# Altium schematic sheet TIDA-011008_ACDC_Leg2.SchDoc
size 431 x 279 mm; Date: Not shown in title block; ApprovedBy: Not shown in title block; CheckedBy: Not shown in title block; Author: Not shown in title block; CompanyName: Not shown in title block; Engineer: Not shown in title block; Organization: Not shown in title block; Address1: Not shown in title block; Address2: Not shown in title block; Address3: Not shown in title block; Address4: Not shown in title block; DocumentNumber: 1; Revision: Use project parameter SCH_Rev; SheetNumber: 5; SheetTotal: 12; PageSetup: Record=PageOptions¦CenterHorizontal=True¦CenterVertical=True¦PrintScale=1.00¦XCorrection=1.00¦YCorrection=1.00¦PrintKind=0¦BorderSize=5000000¦LeftOffset=0¦BottomOffset=0¦Orientation=2¦PaperLength=1000¦PaperWidth=1000¦Scale=100¦PaperSource=15¦PrintQuality=600¦MediaType=1¦DitherType=10¦PaperKind=Letter¦PrintScaleMode=1
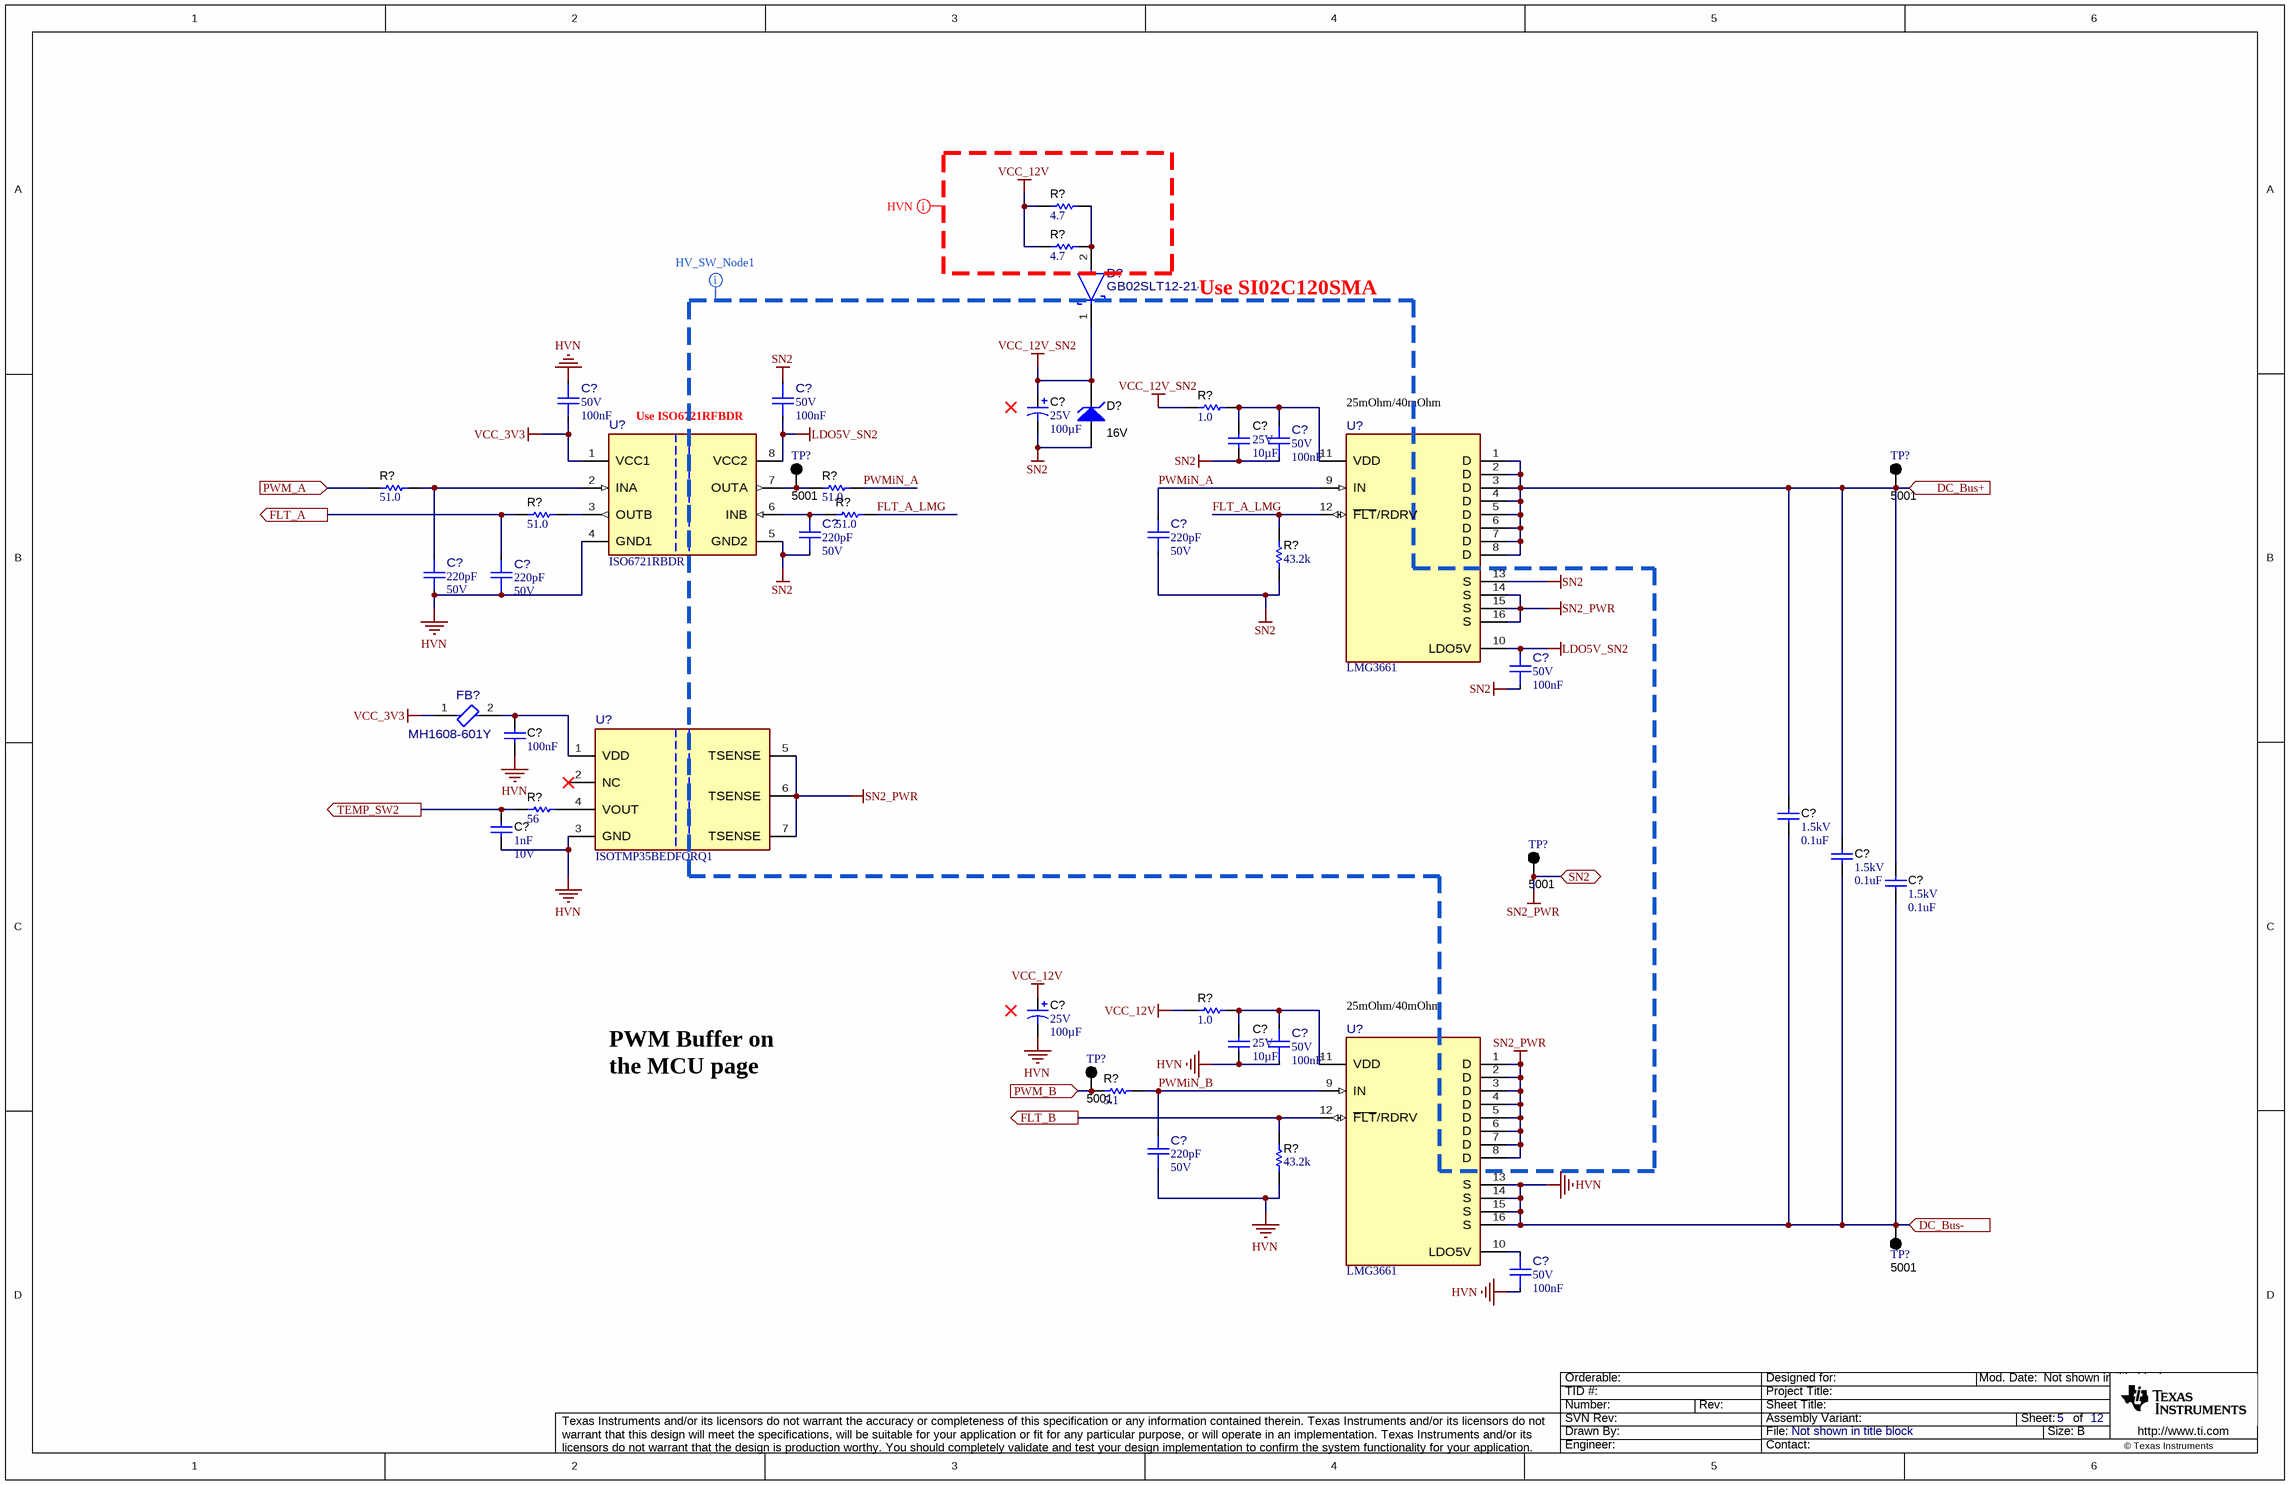
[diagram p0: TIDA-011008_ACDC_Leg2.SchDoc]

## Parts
(Parts that share a designator on the sheet are numbered #1, #2 ... from top to bottom, then left to right.)
C?#1  VDC_V: 50V  Cap_F: 100nF  [FP-GCM188R71H104KA57J_0603-MFG]  (hidden comment: GCM188R71H104KA57J)
C?#2  VDC_V: 50V  Cap_F: 100nF  [FP-GCM188R71H104KA57J_0603-MFG]  (hidden comment: GCM188R71H104KA57J)
C?#3  VDC_V: 25V  ValueDisplayed: 100µF  [UWT_630x770]  (hidden comment: UWT1E101MCL1GS)
C?#4  VDC_V: 25V  ValueDisplayed: 10µF  [1206_180]  (hidden comment: TMK316AB7106KLHT)
C?#5  VDC_V: 50V  Cap_F: 100nF  [FP-GCM188R71H104KA57J_0603-MFG]  (hidden comment: GCM188R71H104KA57J)
C?#6  ValueDisplayed: 220pF  VDC_V: 50V  [FP-C0603C221J5GAC7867_0603-MFG]  (hidden comment: C0603C221J5GAC7867)
C?#7  ValueDisplayed: 220pF  VDC_V: 50V  [FP-C0603C221J5GAC7867_0603-MFG]  (hidden comment: C0603C221J5GAC7867)
C?#8  ValueDisplayed: 220pF  VDC_V: 50V  [FP-C0603C221J5GAC7867_0603-MFG]  (hidden comment: C0603C221J5GAC7867)
C?#9  ValueDisplayed: 220pF  VDC_V: 50V  [FP-C0603C221J5GAC7867_0603-MFG]  (hidden comment: C0603C221J5GAC7867)
C?#10  VDC_V: 50V  Cap_F: 100nF  [FP-GCM188R71H104KA57J_0603-MFG]  (hidden comment: GCM188R71H104KA57J)
C?#11  Cap_F: 100nF  [0603]  (hidden comment: 06033C104JAT2A)
C?#12  VDC_V: 1.5kV  ValueDisplayed: 0.1uF  [2225]  (hidden comment: C2225C104KFRACTU)
C?#13  Cap_F: 1nF  VDC_V: 10V  [0603]  (hidden comment: 0603ZC102KAT2A)
C?#14  VDC_V: 1.5kV  ValueDisplayed: 0.1uF  [2225]  (hidden comment: C2225C104KFRACTU)
C?#15  VDC_V: 1.5kV  ValueDisplayed: 0.1uF  [2225]  (hidden comment: C2225C104KFRACTU)
C?#16  VDC_V: 25V  ValueDisplayed: 100µF  [UWT_630x770]  (hidden comment: UWT1E101MCL1GS)
C?#17  VDC_V: 25V  ValueDisplayed: 10µF  [1206_180]  (hidden comment: TMK316AB7106KLHT)
C?#18  VDC_V: 50V  Cap_F: 100nF  [FP-GCM188R71H104KA57J_0603-MFG]  (hidden comment: GCM188R71H104KA57J)
C?#19  ValueDisplayed: 220pF  VDC_V: 50V  [FP-C0603C221J5GAC7867_0603-MFG]  (hidden comment: C0603C221J5GAC7867)
C?#20  VDC_V: 50V  Cap_F: 100nF  [FP-GCM188R71H104KA57J_0603-MFG]  (hidden comment: GCM188R71H104KA57J)
D?#1  GB02SLT12-214  [FP-GB02SLT12-214_DO-214AA-MFG]
D?#2  value 16V  [SOD-123]  (hidden comment: BZT52C16-7-F)
FB?  MH1608-601Y  [FP-MH1608-601Y_0603-MFG]
R?#1  ValueDisplayed: 4.7  [1206]  (hidden comment: CRCW12064R70JNEAHP)
R?#2  ValueDisplayed: 4.7  [1206]  (hidden comment: CRCW12064R70JNEAHP)
R?#3  ValueDisplayed: 1.0  [0603]  (hidden comment: CRCW06031R00JNEA)
R?#4  ValueDisplayed: 51.0  [0603]  (hidden comment: RC0603FR-0751RL)
R?#5  ValueDisplayed: 51.0  [0603]  (hidden comment: RC0603FR-0751RL)
R?#6  ValueDisplayed: 51.0  [0603]  (hidden comment: RC0603FR-0751RL)
R?#7  ValueDisplayed: 51.0  [0603]  (hidden comment: RC0603FR-0751RL)
R?#8  ValueDisplayed: 43.2k  [0603]  (hidden comment: RC0603FR-0743K2L)
R?#9  ValueDisplayed: 56  [0603]  (hidden comment: RG1608P-560-B-T5)
R?#10  ValueDisplayed: 1.0  [0603]  (hidden comment: CRCW06031R00JNEA)
R?#11  ValueDisplayed: 5.1  [0603]  (hidden comment: CRCW06035R10JNEA)
R?#12  ValueDisplayed: 43.2k  [0603]  (hidden comment: RC0603FR-0743K2L)
TP?#1  5001  [Keystone5001]
TP?#2  5001  [Keystone5001]
TP?#3  5001  [Keystone5001]
TP?#4  5001  [Keystone5001]
TP?#5  5001  [Keystone5001]
U?#1  ISO6721RBDR  [D0008A-MFG]
U?#2  LMG3661  [KLF0016A-MFG]
U?#3  ISOTMP35BEDFQRQ1  [DFQ0007A-MFG]
U?#4  LMG3661  [KLF0016A-MFG]

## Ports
DC_Bus+ (in), DC_Bus- (in), FLT_A (out), FLT_B (out), PWM_A (in), PWM_B (in), SN2 (bidir), TEMP_SW2 (out)

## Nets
HVN: C?#1.1 C?#6.2 C?#9.1 C?#11.2 C?#12.2 C?#13.2 C?#14.2 C?#15.2 C?#16.2(-) C?#17.2 C?#18.1 C?#19.1 C?#20.1 R?#12.1 TP?#5.1 U?#1.4(GND1) U?#3.3(GND) U?#4.13(S) U?#4.14(S) U?#4.15(S) U?#4.16(S) ; port DC_Bus-
LDO5V_SN2: C?#2.2 C?#10.2 U?#1.8(VCC2) U?#2.10(LDO5V)
SN2: C?#2.1 C?#3.2(-) C?#4.2 C?#5.1 C?#7.1 C?#8.1 C?#10.1 D?#2.2(A) R?#8.1 U?#1.5(GND2) U?#2.13(S)
SN2_PWR: TP?#3.1 U?#2.14(S) U?#2.15(S) U?#2.16(S) U?#3.5(TSENSE) U?#3.6(TSENSE) U?#3.7(TSENSE) U?#4.1(D) U?#4.2(D) U?#4.3(D) U?#4.4(D) U?#4.5(D) U?#4.6(D) U?#4.7(D) U?#4.8(D) ; port SN2
VCC_3V3: C?#1.2 FB?.1 U?#1.1(VCC1)
VCC_12V: C?#16.1(+) R?#1.1 R?#2.1 R?#10.1
VCC_12V_SN2: C?#3.1(+) D?#1.1(CATHODE) D?#2.1(K) R?#3.1
DC_Bus+: C?#12.1 C?#14.1 C?#15.1 TP?#2.1 U?#2.1(D) U?#2.2(D) U?#2.3(D) U?#2.4(D) U?#2.5(D) U?#2.6(D) U?#2.7(D) U?#2.8(D) ; port DC_Bus+
FLT_A: C?#9.2 R?#6.1 ; port FLT_A
FLT_A_LMG: R?#7.2 R?#8.2 U?#2.12(~{FLT}/RDRV)
FLT_B: R?#12.2 U?#4.12(~{FLT}/RDRV) ; port FLT_B
PWM_A: R?#4.1 ; port PWM_A
PWM_B: R?#11.1 TP?#4.1 ; port PWM_B
PWMiN_A: C?#8.2 R?#5.2 U?#2.9(IN)
PWMiN_B: C?#19.2 R?#11.2 U?#4.9(IN)
TEMP_SW2: C?#13.1 R?#9.1 ; port TEMP_SW2
NetC?#4_1: C?#4.1 C?#5.2 R?#3.2 U?#2.11(VDD)
NetC?#6_1: C?#6.1 R?#4.2 U?#1.2(INA)
NetC?#7_2: C?#7.2 R?#7.1 U?#1.6(INB)
NetC?#11_1: C?#11.1 FB?.2 U?#3.1(VDD)
NetC?#17_1: C?#17.1 C?#18.2 R?#10.2 U?#4.11(VDD)
NetC?#20_2: C?#20.2 U?#4.10(LDO5V)
NetD?#1_2: D?#1.2(ANODE) R?#1.2 R?#2.2
NetR?#5_1: R?#5.1 TP?#1.1 U?#1.7(OUTA)
NetR?#6_2: R?#6.2 U?#1.3(OUTB)
NetR?#9_2: R?#9.2 U?#3.4(VOUT)

Not connected (* = marked no-connect by the designer): U?#3 2(NC)*

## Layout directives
net class HV_SW_Node1: FLT_A_LMG, HVN, LDO5V_SN2, PWMiN_A, PWMiN_B, SN2, SN2_PWR, VCC_12V, VCC_12V_SN2
net class HVN: VCC_12V

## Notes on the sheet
- Use SI02C120SMA
- Use ISO6721RFBDR
- 25mOhm/40mOhm
- PWM Buffer on the MCU page

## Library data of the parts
C?#1 C?#2 C?#5 C?#10 C?#18 C?#20 = CMP-0095617-1: 0603 50 V 0.1 uF X7R ±10% Tolerance SMT Multilayer Ceramic Capacitor; Manufacturer: Murata; TempCo: 15%; SizeZ_mm: 0.9mm; AEC Qualified: No; ValueDisplayed: 0.1uF; Value: 100nF
C?#3 C?#16 = CMP-0081462-1: CAP, AL, 100 µF, 25 V, +/- 20%, SMD; Manufacturer: Nichicon; TaMin_C: -55°C; Polarized: Y; SizeAreaWB_mm2: 77.4; U/M: EA; Value: 100uF; TaMax_C: 105°C; SizeZ_mm: 8; SizeX_mm: 7; SizeY_mm: 6.6; Cap_Case: 6.3x7.7mm; SizeArea_mm2: 46.2; CompType: Capacitor; AEC Qualified: N; IRMS_A: 91mA; AEC Category: Q200
C?#4 C?#17 = CMP-0750154-1: CAP, CERM, 10 µF, 25 V,+/- 10%, X7R, AEC-Q200 Grade 1, 1206; Manufacturer: Taiyo Yuden; AEC Qualified: Y; SizeZ_mm: 1.8; TaMax_C: 125°C; TaMin_C: -55°C; Cap_Case: 1206; Polarized: N; AEC Grade: 1; SizeY_mm: 1.6; Value: 10uF; SizeX_mm: 3.2; SizeAreaWB_mm2: 10.92; AEC Category: Q200; U/M: EA; SizeArea_mm2: 5.12
C?#6-C?#9 C?#19 = CMP-0045670-1: 220 pF ±5% 50V Ceramic Capacitor C0G, NP0 0603 (1608 Metric); Manufacturer: KEMET; AEC Qualified: No; SizeZ_mm: 0.87mm; TempCo: 30ppm/°C; Value: 220pF
C?#11 = CMP-0006752-5: CAP, CERM, 0.1 uF, 25 V, +/- 5%, X7R, 0603; Manufacturer: AVX; TaMin_C: -55°C; ESR_ohm: 0.05; Polarized: N; SizeAreaWB_mm2: 4.68; Value1: 0.05 ohm; U/M: EA; Value: 0.1uF; TaMax_C: 125°C; SizeZ_mm: 1; SizeX_mm: 1.6; SizeY_mm: 0.8; Value2: 25V; SizeArea_mm2: 1.28; AEC Category: Q200
C?#12 C?#14 C?#15 = CMP-0009331-2: CAP, CERM, 0.1 uF, 1500 V, +/- 10%, X7R, 2225; Manufacturer: Kemet; TaMin_C: -55°C; Polarized: N; SizeAreaWB_mm2: 63.91; Value1: Unknown; U/M: EA; Value: 0.1uF; TaMax_C: 125°C; SizeZ_mm: 2; SizeX_mm: 5.7; SizeY_mm: 6.3; Value2: 1500V; SizeArea_mm2: 35.91; Cap_F: 100nF; AEC Category: Q200
C?#13 = CMP-0006813-4: CAP, CERM, 1000 pF, 10 V, +/- 10%, X7R, 0603; Manufacturer: AVX; TaMin_C: -55°C; Polarized: N; SizeAreaWB_mm2: 4.68; Value1: Unknown; U/M: EA; Value: 1000pF; TaMax_C: 125°C; SizeZ_mm: 1; SizeX_mm: 1.6; SizeY_mm: 0.8; SizeArea_mm2: 1.28; AEC Category: Q200
D?#1 = CMP-0095009-1: Diode Silicon Carbide Schottky 1200 V 2A (DC) Surface Mount DO-214AA; Manufacturer: GeneSiC Semiconductor; Max Surge Forward Current: 20A; ValueDisplayed: 122pF; Vf_V: 1.2kV; Peak Reverse Current: 1uA; SizeZ_mm: 2.44mm; AEC Qualified: No; TJmax_C: 175°C
D?#2 = CMP-0005769-4: Diode, Zener, 16 V, 500 mW, AEC-Q101, SOD-123; Manufacturer: Diodes Inc.; SizeZ_mm: 1.35; AEC Qualified: Y; SizeX_mm: 3.85; AEC Category: Q101; Power_W: 500mW; SizeY_mm: 1.7; Value1: 0.5W; SizeAreaWB_mm2: 13.095; SizeArea_mm2: 6.545; RJA_CperW: 338
FB? = CMP-0037505-1: 600 Ohms @ 100 MHz 1 Power, Signal Line Ferrite Bead 0603 (1608 Metric) 1A 200mOhm; Manufacturer: Bourns; DCR_ohm: 0.2; SizeZ_mm: 1mm; AEC Qualified: No; Impedance At Frequency: 600Ω @ 100MHz; Test Frequency: 100MHz; Tolerance_%: 25%
R?#1 R?#2 = CMP-0018694-3: RES, 4.7, 5%, 0.75 W, AEC-Q200 Grade 0, 1206; Manufacturer: Vishay-Dale; Power_W: 750mW; TempCo: 200 ppm/C; Value_Code: 4R70; Value: 4.7; EIA_Code: E24; SizeX_mm: 3.2; SizeY_mm: 1.6; SizeZ_mm: 1.35; Value2: 0.75W; SizeArea_mm2: 5.12; AEC Qualified: Y; AEC Grade: 0; AEC Category: Q200
R?#3 R?#10 = CMP-0025743-4: RES, 1.0, 5%, 0.1 W, AEC-Q200 Grade 0, 0603; Manufacturer: Vishay-Dale; Power_W: 100mW; TempCo: 200 ppm/C; Value_Code: 1R00; Value: 1.0; EIA_Code: E24; Res_ohm: 1; SizeX_mm: 1.6; SizeY_mm: 0.8; Value2: 0.1W; SizeArea_mm2: 1.28; AEC Qualified: Y; VDC_V: 75V; AEC Category: Q200; AEC Grade: 0
R?#4-R?#7 = CMP-0023169-5: RES, 51.0, 1%, 0.1 W, 0603; Manufacturer: Yageo; Power_W: 100mW; TempCo: 100 ppm/C; Value_Code: 51R0; Value: 51.0; Res_ohm: 51; SizeX_mm: 1.6; SizeY_mm: 0.8; SizeZ_mm: 1; Value2: 0.1W; SizeArea_mm2: 1.28; AEC Qualified: N; VDC_V: 75V; AEC Category: Q200; SizeAreaWB_mm2: 4.68
R?#8 R?#12 = CMP-0023112-5: RES, 43.2 k, 1%, 0.1 W, 0603; Manufacturer: Yageo; Power_W: 100mW; TempCo: 100 ppm/C; Value_Code: 43k2; Value: 43.2k; EIA_Code: E96; SizeX_mm: 1.6; SizeY_mm: 0.8; SizeZ_mm: 1; Value2: 0.1W; SizeArea_mm2: 1.28; AEC Qualified: N; VDC_V: 75V; AEC Category: Q200; SizeAreaWB_mm2: 4.68
R?#9 = CMP-0023572-3: RES, 56, 0.1%, 0.1 W, 0603; Manufacturer: Susumu Co Ltd; Power_W: 100mW; TempCo: 25 ppm/C; Value_Code: 56R0; U/M: EA; Value: 56; SizeX_mm: 1.6; SizeY_mm: 0.8; SizeZ_mm: 1; Value2: 0.1W; SizeArea_mm2: 1.28; VDC_V: 75V; AEC Category: Q200
R?#11 = CMP-0025834-4: RES, 5.1, 5%, 0.1 W, AEC-Q200 Grade 0, 0603; Manufacturer: Vishay-Dale; Power_W: 100mW; TempCo: 200 ppm/C; Value_Code: 5R10; Value: 5.1; EIA_Code: E24; SizeX_mm: 1.6; SizeY_mm: 0.8; SizeZ_mm: 1; Value2: 0.1W; SizeArea_mm2: 1.28; AEC Qualified: Y; VDC_V: 75V; AEC Category: Q200; AEC Grade: 0
TP?#1-TP?#5 = CMP-0055138-2: Test Point, Miniature, Black, TH; Manufacturer: Keystone Electronics; ContactFinish: Silver; CNHeader: FALSE; Green_Lifecycle: Active; Green_REACh: Passed; CT: TRUE
U?#1 = CMP-0127257-1: General-purpose, dual-channel, 1/1 reverse pinout digital isolator 8-SOIC -40 to 125; Manufacturer: Texas Instruments; SizeZ_mm: 1.75mm; AEC Qualified: No; Max Supply Voltage: 5.5V; Min Supply Voltage: 1.71V; Standoff Height: 0.11mm; TaMax_C: +125°C; TaMin_C: -40°C; TJmax_C: +150°C
U?#2 U?#4 = CMP-0124502-1: Manufacturer: Texas Instruments; SizeZ_mm: 2.35mm; Standoff Height: 0mm
U?#3 = CMP-0122473-1: Automotive ±1.5°C, 3-kVRMS Isolated Temperature Sensor With Analog Output With < 2 Seconds Response Time and 500VRMS Working Voltage; Manufacturer: Texas Instruments; SizeZ_mm: 1.75mm; AEC Qualified: Yes; AEC Grade: Grade 0; Max Supply Voltage: 5.5V; Min Supply Voltage: 2.3V; Operating Supply Current: 10uA; Sensor Output: Analog Voltage; Standoff Height: 0.11mm; TaMax_C: +150°C; TaMin_C: -40°C; TJmax_C: +155°C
